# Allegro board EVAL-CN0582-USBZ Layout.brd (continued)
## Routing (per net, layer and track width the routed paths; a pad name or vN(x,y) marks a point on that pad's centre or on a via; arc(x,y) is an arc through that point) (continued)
SPI_MISO_FLASH: length 7.5
  TOP w0.203: R202.2 59.69,39.93 59.69,36.32 60.2,35.81 U2.2 62.87,35.81 R197.2
SPI_MOSI: length 176.8
  TOP w0.152: U18.18 41.12,51.64 41.28,51.79 41.28,52.83 40.64,53.47 v1(39.12,53.47)
  TOP w0.203: U12.8 41.15,64.52 v1(41.02,64.39) ; R201.1 v1(56.13,41.79) ; U20.2 77.48,94.04 76.33,92.89 76.33,92.74 76.07,92.49 76.07,86.89 76.45,86.51 76.45,83.66 77.17,82.95 v1(77.72,82.95) U19.6
  L3_SIG w0.152: v1(77.72,82.95) 77.71,82.93 76.7,82.93 76.29,83.34 74.66,83.34 72.78,81.46 69.31,81.46 59.05,71.2 59.05,55.88 56.64,53.47 v1(56.64,49.4) 56.64,45.13 57.53,44.24 57.53,41.71 57.24,41.43 56.49,41.43 v1(56.13,41.79) 55.88,41.53 55.88,41.2 57.91,39.17 57.91,32.14 59.77,30.29 59.77,25.09 60.93,23.93 60.93,18.2 60.2,17.46 60.2,13.72 56.16,9.68 43.44,9.68 42.81,9.05 42.81,6.87 42.8,6.86
  BOTTOM w0.152: v1(41.02,64.39) 40.72,64.08 40.72,55.07 v1(39.12,53.47) 39.12,52.96 40.23,51.84 47.76,51.84 48.77,50.83 55.47,50.83 56.64,49.66 v1(56.64,49.4) 56.64,48.84 57.76,47.73 U16.12 ; R177.2 TP28.1 37.85,6.22 38.61,5.46 41.4,5.46 42.8,6.86
SPI_MOSI_FLASH: length 5.2
  TOP w0.203: R201.2 56.13,38.61 55.88,38.35 U2.5 R210.2
SPI_RESET_FLASH: length 1.8
  TOP w0.203: U2.7 52.57,35.81 R209.2
SPI_SSN: length 60.3
  TOP w0.152: R175.2 40.13,12.28 40.13,11.43 41.32,10.24 v1(41.32,8.85)
  TOP w0.203: v1(55.09,42.27) 55.22,42.39 55.34,42.39 55.52,42.57 58.22,42.57 58.42,42.37 R204.1
  L3_SIG w0.152: v1(41.32,8.85) 41.57,8.85 43.14,10.41 55.84,10.41 59.49,14.06 59.49,17.68 60.27,18.47 60.27,23.65 59.11,24.82 59.11,30.01 57.23,31.89 57.23,38.82 54.86,41.18 54.86,42.04 v1(55.09,42.27)
SPI_SSN_FLASH: length 9.8
  TOP w0.203: R193.1 63,34.54 U2.1 59.18,34.54 58.42,35.31 R204.2
SPI_WP_FLASH: length 3
  TOP w0.203: U2.3 62.75,37.08 R194.1 R198.2
SS_DM: length 32.9
  TOP w0.152: FL1.C2 13.47,33.18 14.14,32.51 26.74,32.51 31.9,27.34 34.31,27.34 36.36,25.3 38.71,25.3 40.23,23.77 41.17,23.77 41.38,23.99 U1.A10
SS_DP: length 32.9
  TOP w0.152: FL1.C1 12.6,32.78 13.3,32.78 13.97,32.11 26.57,32.11 31.74,26.94 34.15,26.94 36.19,24.89 38.54,24.89 39.95,23.49 39.95,23.48 39.95,23.47 39.96,23.47 40.07,23.37 41.12,23.37 41.3,23.19 U1.A9
SS_RX_M: length 2.5
  BOTTOM w0.152: U35.14 20.01,27.06 20.4,27.06 20.55,26.91 20.55,26.4 21.05,25.91 21.22,25.91 C272.1
SS_RX_P: length 2.4
  BOTTOM w0.152: C271.1 21.48,26.42 21.11,26.42 20.95,26.57 20.95,27.08 20.56,27.47 U35.13
SS_TX_M: length 24.5
  TOP w0.152: v1(21.83,29.41) 22,29.24 24.71,29.24 arc(25.15,29.15) 25.52,28.9 25.56,28.86 arc(25.84,28.45) 25.93,27.96 25.93,23.26 arc(25.99,22.98) 26.14,22.75 27.94,20.96 arc(28.36,20.67) 28.86,20.57 36.68,20.57 arc(37.18,20.67) C141.2
  BOTTOM w0.152: U35.9 20.15,29.07 20.49,29.41 v1(21.83,29.41)
SS_TX_P: length 24.6
  TOP w0.152: v1(21.83,28.69) 21.96,28.83 24.71,28.83 arc(25,28.77) 25.24,28.61 25.27,28.58 arc(25.46,28.29) 25.53,27.96 25.53,23.24 arc(25.61,22.83) 25.84,22.48 27.65,20.67 arc(28.21,20.3) 28.86,20.17 37.05,20.17 arc(37.35,20.11) C142.2
  BOTTOM w0.152: v1(21.83,28.69) 21.52,29 20.66,29 20.32,28.66 20.01,28.66 U35.10
SYNC_IN: length 2.3
  TOP w0.203: R151.1 43.6,40.58 U18.36
SYS_HWRST: length 48.1
  TOP w0.203: v1(30.07,17.65) 29.82,17.4 20.07,17.4 19.29,16.62 19.29,12.56 16.13,9.4 12.32,9.4 11.18,10.53 C206.1 R208.2 9.12,10.38 D17.2 3.07,10.38 S2.2 ; U1.C5 v2(42.68,19.57)
  BOTTOM w0.127: v2(42.68,19.57) 42.44,19.57 42.05,19.18 41.99,19.18 41.98,19.18 41.32,19.18 41.25,19.1
  BOTTOM w0.152: 41.25,19.1 40.53,18.38 38.26,18.38
  BOTTOM w0.203: v1(30.07,17.65) 30.1,17.65 30.83,18.38 38.26,18.38
SYS_POWER: length 19.8
  TOP w0.305: C97.1 18.41,79.03 U13.6 ; v1(17.78,15.16) 17.88,15.27 18.57,15.27 18.67,15.37 18.67,12.89 18.49,12.71 R102.1 ; v1(14.48,72.9) 13.64,72.9 12.83,73.71 12.83,76.33 14.12,77.62 14.12,78.09 14.31,78.28 16.27,78.28 16.89,77.66 U13.8
  TOP w0.457: 30.86,88.52 30.85,88.53 U15.19
  TOP w0.508: v1(23.38,16.5) R274.2 v1(22.61,15.75)
  vias: v1(14.47,73.66) v1(14.48,72.01) v1(18.29,80.39) v1(18.54,15.19) v1(19.05,80.39) v1(23.37,41.91) v1(23.37,41.02) v1(24.26,41.02) v1(24.69,40.43) v1(25.53,64.26) v1(25.53,63.5) v1(29.59,84.84) v1(30.35,86.11) v1(30.35,85.47) v1(30.35,84.84)
TCK: length 65.6
  TOP w0.203: P7.4 23.11,5.59 v1(23.11,3.43) R207.1 ; U1.F6 v2(45.91,21.2)
  L3_SIG w0.127: 45.47,22.73 45.5,22.7 45.5,21.59 45.9,21.2 v2(45.91,21.2)
  L3_SIG w0.203: v1(23.11,3.43) 22.74,3.43 20.93,5.24 20.93,12.17 21.69,12.93 21.69,14.33 22,14.63 22,25.94 24.49,28.43 24.49,29.44 29.46,34.42 37.49,34.42 41.02,30.88 41.02,30.03 42.39,28.66 42.62,28.66 44.2,27.08 44.2,25.84 45.47,24.57 45.47,22.73
TDI: length 53
  TOP w0.203: P7.8 22.48,8.51 22.48,10.28 22.22,10.53 v1(22.22,10.92) R200.1 ; U1.E7 v2(44.28,22)
  L3_SIG w0.127: v2(44.28,22) 43.89,22.39 43.89,25.07 43.56,25.4
  L3_SIG w0.203: 43.56,25.4 42.29,26.67 42.29,27.68 40.26,29.71 40.26,30.57 37.17,33.66 29.78,33.66 25.68,29.55 25.68,15.74 22.22,12.29 v1(22.22,10.92)
TDO: length 52.8
  TOP w0.203: R206.1 v1(30.1,9.01) 29.33,9.01 27.85,7.53 26,7.53 P7.6 ; U1.C10 v2(42.68,24.4)
  L3_SIG w0.127: v2(42.68,24.4) 42.29,24.79 41.25,24.79 41.15,24.89
  L3_SIG w0.203: v1(30.1,9.01) 30.09,9.02 30.01,9.02 26.44,12.58 26.44,29.24 30.1,32.89 36.85,32.89 38.6,31.14 38.6,27.24 39.1,26.75 39.1,25.53 39.65,24.97 41.07,24.97 41.15,24.89
TMS: length 60.6
  TOP w0.203: U1.E8 v2(45.11,21.97) ; P7.2 21.72,5.21 v1(21.97,4.95) R229.1
  L3_SIG w0.203: v1(21.97,4.95) 21.31,5.61 21.31,11.91 25.3,15.9 25.3,29.71 29.62,34.04 37.33,34.04 40.64,30.72 40.64,29.87 42.67,27.84 42.67,26.83 44.72,24.78 44.72,22.37 v2(45.11,21.97)
TRIGGER: length 31.9
  TOP w0.203: P14.1 5.97,79.38 6.98,80.39 8.35,80.39 D13.2 9.68,80.42 9.91,80.64 11.18,80.64 R315.1 11.31,79.64 R333.2 R314.2 12.33,78.18 D8.A
  BOTTOM w0.203: P14.1 4.7,81.53 4.7,93.98 P5.1
TRST_N: length 50.5
  TOP w0.203: v2(41.83,25.2) 41.89,25.15 41.94,25.15 U1.B11 ; R199.1 21.08,11.3 21.84,10.54 v1(21.84,9.91) 21.72,9.78 P7.9
  L3_SIG w0.127: 40.52,25.37 41.17,25.37 41.34,25.2 v2(41.83,25.2)
  L3_SIG w0.203: v1(21.84,9.91) 22.35,9.91 22.76,10.31 22.76,11.2 26.06,14.5 26.06,29.4 29.94,33.27 37.01,33.27 38.98,31.3 38.98,27.4 39.48,26.91 39.48,25.69 39.79,25.37 40.52,25.37
TX1_N: length 2.1
  BOTTOM w0.152: U35.6 18.43,29.07 17.73,29.77 17.21,29.77 C253.2
TX1_P: length 2.1
  BOTTOM w0.152: U35.5 18.59,28.66 18.26,28.66 17.56,29.36 17.21,29.36 17.21,29.36 17.16,29.36 C251.2
TX2_N: length 5.2
  TOP w0.152: v1(18.94,29.85) 19.05,29.73 19.05,29.24 18.9,29.08 18.43,29.08 17.72,29.79 16.62,29.79 16.31,30.1 C254.2
  BOTTOM w0.152: U35.7 19.1,29.68 v1(18.94,29.85)
TX2_P: length 5.9
  TOP w0.152: v1(19.67,29.85) 19.46,29.63 19.46,29.07 19.07,28.68 18.27,28.68 18.24,28.7 18.24,28.7 17.55,29.39 16.62,29.39 16.31,29.08 C252.2
  BOTTOM w0.152: U35.8 19.51,29.18 19.51,29.69 v1(19.67,29.85)
TXVDDQ: length 6.4
  TOP w0.203: U1.B5 v2(41.88,19.57)
  BOTTOM w0.356: 40.9,19.93 41.15,19.68 41.77,19.68 v2(41.88,19.57)
  BOTTOM w0.508: E6.1 37.34,20.74 C149.2 39.32,20.74 C156.1 40.9,19.93
UNNAMED_22_ADP5071V2_I1_COMP1: length 5.3
  TOP w0.203: C109.1 R92.1 24.76,98.19 25.04,97.92 26.16,97.92 26.95,97.13 U15.8
UNNAMED_22_ADP5071V2_I1_COMP2: length 5.5
  TOP w0.203: U15.12 26.3,89.27 25.93,88.9 24.2,88.9 23.74,88.44 R94.1 23.62,87.64 C110.1
UNNAMED_22_ADP5071V2_I1_FB1: length 4.1
  TOP w0.203: R96.2 R97.1 27.05,97.64 27.6,97.09 U15.7
UNNAMED_22_ADP5071V2_I1_FB2: length 5
  TOP w0.203: R95.1 24.76,87.62 R93.2 24.9,88.27 25.15,88.52 26.09,88.52 26.29,88.52 26.95,89.18 U15.13
UNNAMED_22_ADP5071V2_I1_INBK: length 2.2
  TOP w0.406: U15.3 30.2,97.18 29.46,97.92
UNNAMED_22_ADP5071V2_I1_SEQ: length 10.4
  TOP w0.203: U15.5 28.9,97.21 28.45,97.66 v1(28.32,97.66)
  BOTTOM w0.203: R82.1 R83.2 22.48,97.79 23.11,97.16 27.81,97.16 v1(28.32,97.66)
UNNAMED_22_ADP5071V2_I1_SLEW: length 6.9
  TOP w0.203: U15.6 28.25,96.98 27.69,97.54 v1(27.69,98.04)
  BOTTOM w0.203: R85.2 R84.1 24.76,98.25 24.97,98.04 v1(27.69,98.04)
UNNAMED_22_ADP5071V2_I1_SS: length 6.4
  TOP w0.203: U15.10 22.43,96.06 21.34,97.16 R276.2
UNNAMED_22_ADP5071V2_I1_SW1: length 3.4
  TOP w0.508: U15.2 30.85,98.53 31.5,99.18
UNNAMED_22_ADP5071V2_I1_SYNC: length 5.5
  TOP w0.203: v1(28.07,98.81) 28.07,98.69 28.98,97.77 28.98,97.72 29.55,97.15 U15.4
  BOTTOM w0.203: v1(28.07,98.81) R87.2 R86.1
UNNAMED_22_ADP5071V2_I1_VREF: length 4.2
  TOP w0.203: U15.14 27.45,89.97 27.45,89.04 26.42,88.01 26.15,88.01 R93.1
  TOP w0.305: R93.1 25.91,87.75 C113.2
UNNAMED_22_ADP7118V2_I56_EN: length 6.2
  TOP w0.305: v1(42.55,98.3) R103.1
  TOP w0.508: U23.3 v1(45.78,98.11)
  BOTTOM w0.508: v1(45.78,98.11) 44.83,97.16 43.18,97.16 42.55,97.79 v1(42.55,98.3)
UNNAMED_22_ADP7118V2_I56_SENSE: length 2.7
  TOP w0.305: U23.4 49.3,97.26 49.28,97.24 R109.1 R110.1
UNNAMED_22_ADP7118V2_I56_VIN: length 1.6
  TOP w0.508: R103.2 43.52,99.94 C123.1
UNNAMED_22_ADP7118V2_I56_VOUT: length 5.3
  TOP w0.305: R109.2 v1(51.18,96.52)
  BOTTOM w0.305: v1(51.18,96.52) 51.82,96.52 52.32,97.03 v1(52.32,100.08)
UNNAMED_22_ADP7182V5_I66_ADJ: length 2.7
  TOP w0.305: R106.1 R105.1 51.05,91.19 U24.2
UNNAMED_22_ADP7182V5_I66_EN: length 1.5
  TOP w0.305: U24.3 50.03,92.02 R104.1
UNNAMED_22_ADP7182V5_I66_VOUT: length 4.4
  TOP w0.203: 52.71,89.92 53.47,89.92 53.62,90.07 53.62,92.3 53.47,92.45 R106.2
UNNAMED_22_CAP_I38_N1: length 1.5
  TOP w0.203: C112.1 22.35,87.37 R94.2
UNNAMED_22_CAP_I280_N1: length 1
  TOP w0.508: C111.1 24.76,100.83 R92.2
UNNAMED_22_CAP_I337_N1: length 21.4
  TOP w0.508: 7.49,27.05 7.5,27.06 M1.SH2 6.32,28.16 5.71,27.56 ; 2.6,27.8 M1.SH4 1.55,27.04 ; 1.55,37.54 M1.SH3 3.99,36.78 4.35,36.42 M1.SH1
  BOTTOM w0.508: 6.45,36.42 M1.SH1 7.5,37.18 ; 1.55,27.04 M1.SH4 ; M1.SH4 2.6,27.8 ; M1.SH4 1.55,28.56 ; M1.SH3 2.6,36.78 ; M1.SH3 1.55,37.54 ; M1.SH3 1.55,36.02 ; 6.45,28.16 M1.SH2 ; M1.SH2 7.5,28.92 ; M1.SH2 7.5,27.4
UNNAMED_22_CAP_I400_N1: length 8.2
  TOP w0.152: FL1.C3 13.71,33.58 v1(13.75,33.62)
  BOTTOM w0.152: C253.1 15.61,29.79 14.57,29.79 14,30.37 14,32 12.8,33.2 12.8,33.63 12.93,33.76 13.61,33.76 v1(13.75,33.62)
UNNAMED_22_CAP_I401_N1: length 9.7
  TOP w0.152: v1(13.71,34.33) 13.67,34.29 13.21,34.29 12.9,33.98 FL1.C4
  BOTTOM w0.152: v1(13.71,34.33) 13.54,34.16 12.76,34.16 12.4,33.8 12.4,33.03 13.59,31.83 13.59,30.2 14.4,29.39 15.58,29.39 C251.1
UNNAMED_22_CAP_I402_N1: length 2.4
  TOP w0.152: C252.1 14.17,29.08 13.86,29.39 13.39,29.39 13.17,29.17 12.6,29.17 FL2.C5
UNNAMED_22_CAP_I403_N1: length 2.4
  TOP w0.152: C254.1 13.96,30.1 13.65,29.79 13.22,29.79 13,29.57 FL2.C6
UNNAMED_22_ICCBTU02043_I388_XSD: length 4
  TOP w0.508: v1(16.76,28.3) 16.53,28.3 16.04,27.81 R296.2
  BOTTOM w0.203: U35.3 17.19,27.87 v1(16.76,28.3)
UNNAMED_22_ICPTN5150A_I359_ADR: length 1.6
  BOTTOM w0.203: R316.2 8.94,23.19 U36.5
UNNAMED_22_ICPTN5150A_I359_INTB: length 2
  BOTTOM w0.203: R317.1 9.68,23.59 U36.6
UNNAMED_22_ICPTN5150A_I359_PORT: length 2.9
  BOTTOM w0.203: R100.1 R292.2 9.42,22.39 U36.3
UNNAMED_22_ICPTN5150A_I359_VBUSDET: length 1.6
  BOTTOM w0.203: R101.1 8.73,22.79 U36.4
UNNAMED_23_74125V5_I307_A: length 1.6
  TOP w0.305: R349.1 32.26,32 U42.2
UNNAMED_23_ADLT8330_I322_FBX: length 4
  TOP w0.305: U13.1 16.48,75.76 16.16,75.44 R91.2 R90.1 C311.2
UNNAMED_23_ADLTC3112_I90_IOUT: length 1.9
  TOP w0.203: v1(24.66,65.4) 24.6,65.34 U30.8
  BOTTOM w0.203: v1(24.66,65.4) 24.64,65.38 R295.1
UNNAMED_23_ADLTC3112_I90_PWM: length 2.1
  TOP w0.152: U30.19 17.34,61.44 16.35,60.45 R294.1
UNNAMED_23_ADP1708_I291_ADJ: length 2.8
  TOP w0.203: R107.1 R108.2 13.62,12.08 U14.8
UNNAMED_23_ADP1708_I291_EN: length 1.6
  TOP w0.203: U14.1 16.36,13.72 16.48,13.72 16.48,13.69 17.91,13.69 R102.2
UNNAMED_23_ADP1708_I291_OUT: length 4.8
  TOP w0.203: R107.2 11.42,11.06 11.28,11.2 11.28,14.71 11.3,14.73
UNNAMED_23_ADP1708_I291_SENSE: length 1.8
  TOP w0.203: U14.7 13.16,14.23 12.27,13.34 R113.2
UNNAMED_23_ADP7118V2_I83_EN: length 4
  TOP w0.305: U31.3 33.25,56.24 33.47,56.45 33.47,57.91 33.24,58.14 U31.1
UNNAMED_23_ADP7118V2_I83_SENSE: length 3.2
  TOP w0.305: R158.2 R278.1 35.58,56.24 U31.4
UNNAMED_23_ADP7118V2_I83_VOUT: length 9.6
  TOP w0.305: R158.1 37.73,54.36 38.21,54.85 38.21,55.82 37.98,56.05 R293.2 ; U31.5 34.65,60.05 TP55.1
  TOP w0.508: R293.2 37.81,58.21 C227.1 34.72,58.21 U31.5
UNNAMED_23_ADP7142_I123_EN: length 9.2
  TOP w0.203: 28.96,80.07 28.96,81.28 29.08,81.41 32.77,81.41 33.16,81.01 U11.4
UNNAMED_23_ADP7142_I123_SS: length 1.3
  TOP w0.203: U11.5 C92.2
UNNAMED_23_CAP_I58_N2: length 1.9
  TOP w0.305: U30.18 17.28,62.09 16.79,61.59 C218.2
UNNAMED_23_CAP_I63_N2: length 7.5
  TOP w0.203: 30.35,65.53 30.35,63.37 31.37,62.36 31.37,60.41 31.17,60.21 C223.2 30.47,60.07 R289.2
UNNAMED_23_CAP_I65_N1: length 3
  TOP w0.203: C221.1 25.41,61.09 C222.2 25.05,61.44 U30.2
UNNAMED_23_CAP_I65_N2: length 1.1
  TOP w0.203: C221.2 R288.2
UNNAMED_23_CAP_I72_N1: length 1
  TOP w0.203: C223.1 30.6,61.21 R291.1
UNNAMED_23_CAP_I109_N1: length 1.1
  TOP w0.203: C95.1 33.74,71.73 R277.2
UNNAMED_23_CAP_I117_N2: length 1.6
  TOP w0.305: C100.2 17.91,78.49 U13.7
UNNAMED_23_CAP_I249_N2: length 3.1
  TOP w0.203: v1(19.68,44.32) v1(20.45,44.32) ; v1(19.81,48.13) v1(20.57,48.13)
  TOP w0.508: Q7.3 v1(19.68,44.32) ; Q8.3 v1(19.81,48.13)
  vias: v1(19.68,39.75) v1(20.32,39.75) v1(21.07,39.74)
UNNAMED_23_CAP_I257_N1: length 6.2
  TOP w0.508: Q7.2 17.97,45.26 C261.1 R328.1 16.07,45.26 Q5.2
UNNAMED_23_CAP_I257_N2: length 7.6
  TOP w0.508: Q5.1 16.07,43.38 R328.2 C261.2 17.97,43.38 Q7.1 22.29,43.38 22.35,43.44
UNNAMED_23_CAP_I260_N1: length 6.2
  TOP w0.508: Q6.2 16.07,49.07 C262.1 R329.1 17.97,49.07 Q8.2
UNNAMED_23_CAP_I260_N2: length 9.5
  TOP w0.203: 22.1,49.16 R327.1
  TOP w0.508: 22.1,49.16 22.1,47.55 21.74,47.19 Q8.1 17.97,47.19 R329.2 C262.2 16.07,47.19 Q6.1
UNNAMED_23_CAP_I272_N2: length 4.8
  TOP w0.508: R325.2 16.17,54.1 C260.2 16.94,53.33 R348.2 19.24,53.33 Q4.G
UNNAMED_23_CAP_I299_N1: length 0.9
  TOP w0.508: C287.1 R336.1
UNNAMED_23_CN2P_I240_N1: length 3.7
  TOP w0.508: 2.82,53.72 P12.1 ; P12.1 4.06,54.97 ; P12.1 5.31,53.72
UNNAMED_23_DIOLED_I278_P: length 1.5
  TOP w0.305: DS1.A R111.1
UNNAMED_23_RES_I270_N2: length 5.6
  TOP w0.508: R297.2 20.71,58.23 20.7,58.22 20.7,57.78 20.39,57.47 Q3.G 18.21,56.52 Q1.D
UNNAMED_23_RES_I295_N2: length 2.6
  TOP w0.508: Q4.D 22.35,51.93 R327.2
UNNAMED_23_RES_I296_N2: length 13.4
  TOP w0.508: Q3.D 22.99,56.52 23.49,56.01 23.49,46.74 22.35,45.59 R326.2
UNNAMED_24_ADA49451_I49_: length 3.6
  TOP w0.203: U9.4 75.96,73.82 77.08,74.94 C76.2 77.75,74.96 R70.2
UNNAMED_24_ADA49451_I49__1: length 3.4
  TOP w0.203: U9.3 76.42,73.32 77.04,73.94 C76.1 78.63,73.94 R66.2
UNNAMED_24_ADA49451_I49__2: length 3.4
  TOP w0.203: R65.2 78.67,72.14 C75.1 77.09,72.14 76.41,72.82 U9.2
UNNAMED_24_ADA49451_I49__3: length 3.6
  TOP w0.203: R69.2 78.63,71.14 C75.2 77.14,71.14 75.96,72.32 U9.1
UNNAMED_24_ADA49451_I49__4: length 1.8
  TOP w0.203: U9.10 71.58,73.32 R74.1
UNNAMED_24_ADA49451_I49__5: length 1.8
  TOP w0.203: R73.1 71.61,72.82 U9.11
UNNAMED_24_ADA49451_I63_: length 3.4
  TOP w0.203: R67.2 78.55,51.19 C77.1 76.96,51.19 76.29,51.86 U10.2
UNNAMED_24_ADA49451_I63__1: length 3.4
  TOP w0.203: R68.2 78.5,52.98 C78.1 76.91,52.98 76.29,52.36 U10.3
UNNAMED_24_ADA49451_I63__2: length 3.6
  TOP w0.203: R71.2 78.5,50.19 C77.2 77.01,50.19 75.83,51.36 U10.1
UNNAMED_24_ADA49451_I63__3: length 3.6
  TOP w0.203: U10.4 75.83,52.86 76.95,53.98 C78.2 77.62,54.01 R72.2
UNNAMED_24_ADA49451_I63__4: length 1.8
  TOP w0.203: R76.1 71.45,52.36 U10.10
UNNAMED_24_ADA49451_I63__5: length 1.8
  TOP w0.203: R75.1 71.48,51.86 U10.11
UNNAMED_24_ADLTC6910X_I158_AGND: length 5.4
  TOP w0.203: A10.2 v1(84.76,76.68)
  BOTTOM w0.203: R304.1 R298.1 R302.2 84.71,76.63 v1(84.76,76.68) 84.83,76.62 C226.1
UNNAMED_24_ADLTC6910X_I158_IN: length 8.7
  TOP w0.203: A10.3 85.78,77.31 A3.1 88.86,77.31 89.12,77.05 89.12,74.81 88.9,74.6 88.27,74.6 87.89,74.22 R55.2 C65.2
UNNAMED_24_ADLTC6910X_I158_OUT: length 3.6
  TOP w0.203: R57.1 86.86,74.35 v1(86.49,74.72) 85.75,75.46 A10.1
  BOTTOM w0.305: TP11.1 v1(86.49,74.72)
UNNAMED_24_ADLTC6910X_I163_AGND: length 5.4
  TOP w0.203: A11.2 v1(84.64,55.73)
  BOTTOM w0.203: C228.1 84.7,55.67 v1(84.64,55.73) 84.58,55.67 R303.2 R299.1 R305.1
UNNAMED_24_ADLTC6910X_I163_IN: length 8.8
  TOP w0.203: A11.3 85.65,56.35 A4.1 88.73,56.35 88.99,56.09 88.99,53.86 88.77,53.64 87.97,53.64 87.76,53.44 R56.2 C66.2
UNNAMED_24_ADLTC6910X_I163_OUT: length 3.6
  TOP w0.203: R58.1 86.73,53.4 v1(86.37,53.76) 85.63,54.5 A11.1
  BOTTOM w0.203: TP12.1 86.49,53.64 v1(86.37,53.76)
UNNAMED_24_CAP_I13_N2: length 2.9
  TOP w0.203: R43.2 C59.2 98.77,67.21 97.97,68.01 U7.5
UNNAMED_24_CAP_I35_N1: length 4
  TOP w0.203: C65.1 R55.1 R53.2 89.92,74.3 90.46,74.84 A3.4
UNNAMED_24_CAP_I37_N1: length 2.6
  TOP w0.203: R57.2 C71.1 R62.1
UNNAMED_24_CAP_I37_N2: length 2.5
  TOP w0.203: R59.2 C71.2 R61.1
UNNAMED_24_CAP_I42_N1: length 3.7
  TOP w0.203: R62.2 C73.1 R66.1 R70.1
UNNAMED_24_CAP_I42_N2: length 3.8
  TOP w0.203: R61.2 C73.2 R65.1 R69.1
UNNAMED_24_CAP_I67_N1: length 3.7
  TOP w0.203: R72.1 R68.1 C74.1 R64.2
UNNAMED_24_CAP_I67_N2: length 3.8
  TOP w0.203: R71.1 R67.1 C74.2 R63.2
UNNAMED_24_CAP_I71_N1: length 2.6
  TOP w0.203: R64.1 C72.1 R58.2
UNNAMED_24_CAP_I71_N2: length 2.5
  TOP w0.203: R60.2 C72.2 R63.1
UNNAMED_24_CAP_I83_N2: length 2.9
  TOP w0.203: R44.2 C60.2 98.64,58.95 97.84,59.75 U8.5
UNNAMED_24_CAP_I86_N1: length 4
  TOP w0.203: C66.1 R56.1 R54.2 89.8,53.35 90.34,53.89 A4.4
UNNAMED_24_RES_I182_N2: length 3.7
  TOP w0.508: A17.3 C307.1 87.69,65.46 R78.2 R7.2
UNNAMED_24_RES_I184_N2: length 3.7
  TOP w0.508: R264.2 R265.2 87.69,44.89 C308.1 A16.3
UNNAMED_25_ADA49451_I78_: length 3.6
  TOP w0.203: R35.2 78.63,32.63 C43.2 77.14,32.63 75.96,33.81 U21.1
UNNAMED_25_ADA49451_I78__1: length 3.6
  TOP w0.203: U21.4 75.96,35.31 77.08,36.43 C44.2 77.75,36.45 R36.2
UNNAMED_25_ADA49451_I78__2: length 3.4
  TOP w0.203: R31.2 78.67,33.63 C43.1 77.09,33.63 76.41,34.31 U21.2
UNNAMED_25_ADA49451_I78__3: length 3.4
  TOP w0.203: U21.3 76.42,34.81 77.04,35.43 C44.1 78.63,35.43 R32.2
UNNAMED_25_ADA49451_I78__4: length 1.8
  TOP w0.203: R40.1 71.58,34.81 U21.10
UNNAMED_25_ADA49451_I78__5: length 1.8
  TOP w0.203: U21.11 71.61,34.31 R39.1
UNNAMED_25_ADA49451_I92_: length 3.4
  TOP w0.203: R33.2 78.55,12.68 C45.1 76.96,12.68 76.29,13.35 U6.2
UNNAMED_25_ADA49451_I92__1: length 3.4
  TOP w0.203: R34.2 78.5,14.47 C46.1 76.91,14.47 76.29,13.85 U6.3
UNNAMED_25_ADA49451_I92__2: length 3.6
  TOP w0.203: U6.1 75.83,12.85 77.01,11.68 C45.2 78.5,11.68 R37.2
UNNAMED_25_ADA49451_I92__3: length 3.6
  TOP w0.203: R38.2 77.62,15.49 C46.2 76.95,15.47 75.83,14.35 U6.4
UNNAMED_25_ADA49451_I92__4: length 1.8
  TOP w0.203: R42.1 71.45,13.85 U6.10
UNNAMED_25_ADA49451_I92__5: length 1.8
  TOP w0.203: U6.11 71.48,13.35 R41.1
UNNAMED_25_ADLTC6910X_I163_AGND: length 5.4
  TOP w0.203: A12.2 v1(84.76,38.17)
  BOTTOM w0.203: R309.1 R300.1 R307.2 84.71,38.12 v1(84.76,38.17) 84.83,38.11 C231.1
UNNAMED_25_ADLTC6910X_I163_IN: length 8.7
  TOP w0.203: A12.3 85.78,38.8 A1.1 88.86,38.8 89.12,38.54 89.12,36.3 88.9,36.08 88.27,36.08 87.89,35.71 R21.2 C33.2
UNNAMED_25_ADLTC6910X_I163_OUT: length 3.6
  TOP w0.203: A12.1 85.75,36.94 v1(86.49,36.21) 86.86,35.84 R23.1
  BOTTOM w0.305: TP5.1 v1(86.49,36.21)
UNNAMED_25_ADLTC6910X_I168_AGND: length 5.4
  TOP w0.203: A13.2 v1(84.64,17.22)
  BOTTOM w0.203: C232.1 84.7,17.15 v1(84.64,17.22) 84.58,17.16 R306.2 R301.1 R308.1
UNNAMED_25_ADLTC6910X_I168_IN: length 8.7
  TOP w0.203: A13.3 85.65,17.84 A2.1 88.73,17.84 88.99,17.58 88.99,15.35 88.77,15.13 88.14,15.13 87.76,14.76 R22.2 C34.2
UNNAMED_25_ADLTC6910X_I168_OUT: length 3.6
  TOP w0.203: R24.1 86.73,14.88 v1(86.37,15.25) 85.63,15.99 A13.1
  BOTTOM w0.203: v1(86.37,15.25) 86.49,15.13 TP4.1
UNNAMED_25_CAP_I38_N1: length 4
  TOP w0.203: C33.1 R21.1 R19.2 89.92,35.82 90.46,36.36 A1.4
UNNAMED_25_CAP_I41_N2: length 2.9
  TOP w0.203: U4.5 97.97,29.49 98.77,28.69 C27.2 R9.2
UNNAMED_25_CAP_I53_N1: length 2.6
  TOP w0.203: R24.2 C40.1 R30.1
UNNAMED_25_CAP_I53_N2: length 2.5
  TOP w0.203: R26.2 C40.2 R29.1
UNNAMED_25_CAP_I56_N1: length 3.7
  TOP w0.203: R30.2 C42.1 R34.1 R38.1
UNNAMED_25_CAP_I56_N2: length 3.8
  TOP w0.203: R29.2 C42.2 R33.1 R37.1
UNNAMED_25_CAP_I70_N1: length 2.6
  TOP w0.203: R23.2 C39.1 R28.1
UNNAMED_25_CAP_I70_N2: length 2.5
  TOP w0.203: R27.1 C39.2 R25.2
UNNAMED_25_CAP_I74_N1: length 3.7
  TOP w0.203: R36.1 R32.1 C41.1 R28.2
UNNAMED_25_CAP_I74_N2: length 3.8
  TOP w0.203: R27.2 C41.2 R31.1 R35.1
UNNAMED_25_CAP_I94_N2: length 2.9
  TOP w0.203: R10.2 C28.2 98.64,20.44 97.84,21.24 U5.5
UNNAMED_25_RES_I15_N2: length 4
  TOP w0.203: C34.1 R22.1 R20.2 89.8,14.99 90.34,15.53 A2.4
UNNAMED_25_RES_I181_N1: length 2.3
  TOP w0.305: Q9.D 102.85,7.49 R341.1
UNNAMED_25_RES_I185_N2: length 3.7
  TOP w0.508: R358.2 R359.2 87.82,27.33 C310.1 A18.3
UNNAMED_25_RES_I187_N2: length 3.7
  TOP w0.508: R266.2 R267.2 87.69,5.87 C309.1 A19.3
UNNAMED_26_ADG5436_I1_EN: length 2.3
  TOP w0.305: U22.12 93.09,69.58 R279.2
UNNAMED_26_ADG5436_I1_S1B: length 2.4
  TOP w0.203: C119.2 98.49,72.52 U22.2
UNNAMED_26_ADG5436_I1_S2B: length 2.3
  TOP w0.305: U22.10 93.07,73.15 91.82,73.15 91.39,72.72 R281.2
UNNAMED_26_ADG5436_I1_VSS: length 3.7
  TOP w0.203: U22.3 97.78,73.17 99.05,74.45 R360.2 R362.1
UNNAMED_26_ADG5436_I17_EN: length 2.3
  TOP w0.305: R280.2 92.96,48.62 U27.12
UNNAMED_26_ADG5436_I17_S1B: length 2.5
  TOP w0.203: U27.2 98.43,51.56 C120.2
UNNAMED_26_ADG5436_I17_S2B: length 2.3
  TOP w0.203: U27.10 92.94,52.2 91.69,52.2 91.26,51.76 R282.2
UNNAMED_26_ADG5436_I17_VSS: length 3.7
  TOP w0.203: U27.3 97.61,52.21 R361.2 R363.1
UNNAMED_26_ADG5436_I20_EN: length 2.3
  TOP w0.305: R283.2 93.09,31.07 U28.12
UNNAMED_26_ADG5436_I20_S1B: length 2.5
  TOP w0.203: C131.2 98.59,34.01 U28.2
UNNAMED_26_ADG5436_I20_S2B: length 2.3
  TOP w0.203: U28.10 93.07,34.64 91.82,34.64 91.39,34.21 R285.2
UNNAMED_26_ADG5436_I20_VSS: length 3.5
  TOP w0.203: U28.3 97.48,34.66 R364.2 R366.1
UNNAMED_26_ADG5436_I29_EN: length 2.3
  TOP w0.305: U29.12 92.96,10.11 R284.2
UNNAMED_26_ADG5436_I29_S1B: length 2.4
  TOP w0.203: C153.2 98.4,13.05 U29.2
UNNAMED_26_ADG5436_I29_S2B: length 2.3
  TOP w0.203: U29.10 92.94,13.69 91.69,13.69 91.26,13.25 R286.2
UNNAMED_26_ADG5436_I29_VSS: length 3.5
  TOP w0.203: R367.1 R365.2 97.58,13.7 U29.3
UNNAMED_27_AD55X3_I1_IOUT: length 18.9
  TOP w0.203: U20.5 73.61,95.34 73.44,95.5 73.4,95.5 73.34,95.56 71.06,95.56 70.36,96.27 70.36,98.55 70.61,98.81 C193.2 72.02,100.53 72.58,101.09 74.3,101.09 77.16,98.23 A8.2
UNNAMED_27_AD9833_I8_CAP: length 4.3
  TOP w0.305: CAP2.5.1 70.73,84.07 C181.2 C180.1 73.14,83.95 U19.3
UNNAMED_27_AD9833_I8_COMP: length 1.6
  TOP w0.203: C178.1 75.05,85.72 74.66,85.33 U19.1
UNNAMED_27_AD9833_I8_MCLK: length 2
  TOP w0.203: R153.1 73.76,82.04 U19.5
UNNAMED_27_AD9833_I8_VOUT: length 3.7
  TOP w0.305: R154.1 79.37,85.72 79.01,85.36 U19.10 79.99,84.95 v1(80.14,85.09)
  BOTTOM w0.305: R343.1 79.78,85.45 v1(80.14,85.09)
UNNAMED_27_ADA45221_I217_: length 6.9
  TOP w0.305: v1(80.01,88.65) R155.2 R156.1 80.47,89.97 A7.2
  BOTTOM w0.305: C291.1 79.83,86.49 80.14,86.79 80.14,88.52 v1(80.01,88.65) 80.02,88.65 C292.1
UNNAMED_27_ADA45221_I217__1: length 8.4
  TOP w0.305: A7.3 77.92,90.62 77.22,89.92 v1(77.22,88.52) TP29.1 77.47,87.88 R157.2 R154.2
  BOTTOM w0.305: R344.2 76.57,87.88 v1(77.22,88.52)
UNNAMED_27_ADA45221_I223_: length 6
  TOP w0.305: R312.1 97.29,96.39 96.96,96.72 A14.2 94.04,96.72 R318.2
UNNAMED_27_ADA45221_I223_OUT: length 9.4
  TOP w0.203: R351.2 103.29,94.37 103.05,94.61 TP59.1
  TOP w0.305: R312.2 98.29,95.75 98.61,96.07 A14.6 100.22,96.07 D4.3 TP59.1
UNNAMED_27_ADA45221_I227_: length 5.7
  TOP w0.203: C185.2 92.34,90.85 94.46,90.85 94.47,90.86 A5.3
  TOP w0.305: R160.2 91.64,90.26 C185.2
UNNAMED_27_ADG1219_I151_D: length 5.2
  TOP w0.203: U32.6 92.32,96.07 TP57.1 92.57,96.07 A14.3
UNNAMED_27_ADG1219_I151_EN: length 2.9
  TOP w0.305: R310.2 87.89,98.8 88.06,98.63 U32.1
UNNAMED_27_ADG1219_I151_SB: length 20
  TOP w0.305: v1(103.21,90.84) C216.1 102.09,90.86 A5.6 ; U32.5 90.5,93.8 TP32.1 90.42,92.96 90.94,92.45 v1(92.01,92.45) R112.1
  BOTTOM w0.305: v1(92.01,92.45) 93.62,90.84 v1(103.21,90.84)
UNNAMED_27_CAP_I189_N2: length 7.9
  TOP w0.305: v1(79.25,88.65) 79.37,88.53 R157.1 80.26,87.88 R148.2 C244.1 82.55,87.62 83.11,87.06 C243.2 R311.1
  BOTTOM w0.305: v1(79.25,88.65) 79.37,88.53 R345.1
UNNAMED_27_CAP_I238_N2: length 1
  BOTTOM w0.305: R343.2 C291.2
UNNAMED_27_CAP_I250_N2: length 16.7
  TOP w0.305: v1(90.17,87.76) R160.1 R159.2 ; C216.2 v1(103.04,89.24)
  BOTTOM w0.305: v1(103.04,89.24) 91.66,89.24 v1(90.17,87.76)
UNNAMED_27_CNBNC2P_I81_CNTR: length 5.6
  TOP w0.203: R351.1 D5.2 D4.4
  TOP w0.305: D5.2 J6.1
UNNAMED_27_DIO4PV11_I83_A1: length 1.5
  TOP w0.203: v1(102.74,97.63) D4.1
  BOTTOM w0.305: R121.2 102.74,97.63 v1(102.74,97.63)
UNNAMED_27_DIO4PV11_I83_K2: length 1.1
  TOP w0.203: R228.2 101.99,97.92 D4.2
UNNAMED_27_RES_I13_N2: length 3.4
  TOP w0.203: R153.2 70.46,82.04 70.33,82.17 Y4.3
UNNAMED_27_RES_I119_N2: length 2.8
  TOP w0.203: A5.2 94.04,91.51 R99.2 R112.2
UNNAMED_28_AD568XRV5_I11_VREF: length 4
  BOTTOM w0.305: U16.15 59.95,50.44 C146.2 60.04,52.01 R128.1
UNNAMED_28_AD77684_I28_AVDD1A: length 16.2
  TOP w0.203: U18.4 v1(48.1,55.34)
  TOP w0.254: U18.4 48.1,53.07 48.16,53.01 48.16,52.47 48.1,52.41 U18.45
  BOTTOM w0.305: v1(48.1,55.34) 47.49,55.95 C163.1 C164.1 47.41,57.36 E2.2
UNNAMED_28_AD77684_I28_AVDD2A: length 10.4
  TOP w0.203: U18.60 50.26,50.14 v1(50.04,49.91) ; U18.53 v1(50.24,46.64)
  BOTTOM w0.508: E3.2 47.04,49.78 C166.1 C165.1 49.9,49.78 v1(50.04,49.91) 50.67,49.91 51.05,49.53 51.05,47.45 v1(50.24,46.64)
UNNAMED_28_AD77684_I28_DIN: length 2.2
  TOP w0.203: U18.21 38.45,50.14 R150.2
UNNAMED_28_AD77684_I28_DNC: length 2.2
  TOP w0.203: U18.20 38.38,50.64 R258.1
UNNAMED_28_AD77684_I28_DREGCAP: length 3.2
  TOP w0.203: C171.1 C169.1 42.66,41.62 42.6,41.68 U18.34
UNNAMED_28_AD77684_I28_IOVDD: length 4.7
  TOP w0.203: U18.35 v1(43.1,43.99)
  BOTTOM w0.508: v1(43.1,43.99) 43.19,43.9 C168.2 C167.2 43.19,40.69 E4.1
UNNAMED_28_AD77684_I28_PINN: length 7.1
  TOP w0.203: R149.2 53.6,49.2 53.93,49.53 55,49.53 ; U18.57 52.83,48.64
  TOP w0.305: 55,49.53 55.63,49.53 56.9,50.8 TP7.1
  TOP w0.508: 52.83,48.64 52.83,48.64 R149.2
UNNAMED_28_AD77684_I28_REG1CAPA: length 3.2
  TOP w0.254: C175.1 C174.1 53.3,50.64 U18.61
UNNAMED_28_AD77684_I28_REG2CAPB: length 3.3
  TOP w0.254: 53.21,46.14 U18.52
  TOP w0.508: 53.21,46.14 53.59,45.76 C172.1 C173.1
UNNAMED_28_AD77684_I28_SYNCOUTN: length 2.3
  TOP w0.203: U18.38 44.6,41.58 44.69,41.49 R151.2
UNNAMED_28_ADA48071_I285_: length 10.7
  TOP w0.508: A6.4 v1(53.61,56.71) ; R139.1 49.24,59.26 C152.1 v1(49.24,61.35)
  L3_SIG w0.508: v1(49.24,61.35) 49.24,60.24 52.77,56.71 v1(53.61,56.71)
UNNAMED_28_ADA48071_I285__1: length 1.4
  TOP w0.508: R132.2 50.98,56.71 A6.3
UNNAMED_28_ADA48071_I292_: length 2.7
  TOP w0.635: R143.2 R142.1 50.73,66.23 A9.4
UNNAMED_28_ADA48071_I307_: length 2.6
  TOP w0.508: R195.2 C101.1 57.58,60.18 A15.4
UNNAMED_28_ADA48071_I307_DISABLEN: length 1.6
  TOP w0.508: R319.1 57.41,59.11 58.49,59.11 A15.5
UNNAMED_28_ADA48071_I307_VOUT: length 12.7
  TOP w0.508: C101.2 R195.1 v1(56.27,61.91) ; v1(62.49,57.37) R253.1 62.43,58.28 A15.1
  BOTTOM w0.508: v1(56.27,61.91) 58.39,61.91 62.49,57.81 v1(62.49,57.37)
UNNAMED_28_CAP_I178_N1: length 6.4
  TOP w0.508: 29.34,46.86 C12.1 30.49,46.31 E16.2 ; 29.34,46.86 R6.1 ; 29.34,46.86 29.29,46.82 Y3.4
UNNAMED_28_CAP_I209_N1: length 5
  TOP w0.508: E17.2 34.41,51.4 C13.1 R77.1 34.41,46.99 Y5.4
UNNAMED_28_CAP_I254_N2: length 3
  TOP w0.508: C152.2 50.84,58.88 R138.1 51.04,58.61 A6.1
UNNAMED_28_CAP_I282_N2: length 3
  TOP w0.635: C154.2 58.84,66.2 R131.2 R135.1
UNNAMED_28_NCTESTPAD_I237_N1: length 5.3
  TOP w0.203: R256.1 55.51,47.51 57.41,49.41 TP18.1
  TOP w0.508: R257.1 R256.1 55.51,46.23 R255.2
UNNAMED_28_RES_I152_N2: length 2.5
  TOP w0.635: R135.2 56.9,66.3 R254.1 55.81,66.23 A9.3
UNNAMED_28_RES_I334_N1: length 1.8
  TOP w0.203: R373.1 Y3.3
UNNAMED_28_RES_I335_N2: length 3
  TOP w0.203: Q10.G 29.41,48.45 29.84,48.01 R374.1 R372.2
UNNAMED_28_RES_I336_N2: length 3.7
  TOP w0.203: Y5.1 33.41,46.73 R77.2 32.64,48.26 32.38,48.01 R374.2
UNNAMED_28_RES_I338_N2: length 4.8
  TOP w0.203: Y3.1 27.09,46.83 R6.2 26.81,47.11 Q10.D
UNNAMED_28_RES_I341_N1: length 1.7
  TOP w0.203: Y5.3 34.67,44.71 R375.1
UNNAMED_29_ADP1708_I198_ADJ: length 2.8
  TOP w0.203: U26.8 30.48,15.86 R227.1 30.95,16.34 R226.1
UNNAMED_29_ADP1708_I198_EN: length 1.4
  TOP w0.203: R224.1 25.65,15.86 U26.1
UNNAMED_29_ADP1708_I198_IN: length 2.2
  TOP w0.203: R274.1 R275.1 25.39,14.6 R224.2
UNNAMED_29_ADP1708_I198_SENSE: length 1.5
  TOP w0.203: U26.7 30.56,15.36 R225.2
UNNAMED_29_CAP_I53_N1: length 3
  TOP w0.152: U1.A5 41.16,19.99 40.96,20.18 39.19,20.18 arc(38.87,20.12) C142.1
UNNAMED_29_CAP_I54_N1: length 3.1
  TOP w0.152: U1.A6 41.16,20.79 40.96,20.59 39.48,20.59 arc(39.01,20.68) C141.1
UNNAMED_29_CAP_I143_N1: length 11.9
  TOP w0.152: U1.E10 44.28,24.4 44.28,24.96 43.25,25.98
  TOP w0.203: D6.C 39.24,30.93 C90.1 R231.2 40.27,28.19 42.29,26.16 42.82,26.16 43,25.98 43.25,25.98
UNNAMED_29_CAP_I208_N2: length 24.9
  TOP w0.152: v1(24.26,24.38) 24.09,24.21 arc(24.04,24.15) 24.03,24.08 24.03,21.84 arc(24.22,20.88) 24.76,20.07 arc(25.81,19.37) 27.03,19.13 ; 27.03,19.13 27.03,19.13 ; 27.03,19.13 arc(27.03,19.13) 27.03,19.13 ; 27.03,19.13 34.54,19.13 arc(34.78,19.1) 35.02,19.02 arc(35.07,19) 35.14,18.99 40.96,18.99 41.16,19.19 U1.A4
  BOTTOM w0.152: C271.2 22.95,26.19 23.56,26.19 24.02,25.73 24.02,25.1 24.26,24.86 v1(24.26,24.38)
UNNAMED_29_CAP_I209_N2: length 24.8
  TOP w0.152: v1(23.37,24.38) 23.62,24.13 23.62,24.13 arc(23.62,24.1) 23.62,24.08 23.62,21.84 arc(23.84,20.73) 24.48,19.78 arc(25.65,19) 27.03,18.72 34.54,18.72 arc(34.69,18.7) 34.84,18.65 arc(34.98,18.6) 35.14,18.58 40.96,18.58 41.16,18.39 U1.A3
  BOTTOM w0.152: C272.2 22.85,25.78 23.39,25.78 23.61,25.56 23.61,25.1 23.37,24.86 v1(23.37,24.38)
UNNAMED_29_DIOSCHOTTKY_I142_P: length 33.8
  TOP w0.508: P8.2 58.8,24.77 59.44,24.13 61.59,24.13 62.1,24.64 62.1,31.24 61.09,32.26 52.45,32.26 51.64,33.07 42.21,33.07 41.27,32.12 R231.1
UNNAMED_29_ICCYUSB301X_I1_CLKIN: length 6.2
  TOP w0.203: U1.D7 v2(43.48,22)
  BOTTOM w0.127: 41.22,24.36 41.4,24.18 41.54,24.18 41.72,23.99 42.05,23.99 42.28,23.76 42.28,23.39 42.47,23.21 42.94,23.21 43.08,23.07 43.08,22.41 v2(43.48,22)
  BOTTOM w0.203: 41.22,24.36 40.56,25.02 TP1.1
UNNAMED_29_ICCYUSB301X_I1_GPIO: length 7.5
  TOP w0.203: U1.J6 v2(48.31,21.2)
  BOTTOM w0.152: v2(48.31,21.2) 48.86,20.65 51.01,20.65 52.92,22.56 R140.2
UNNAMED_29_ICCYUSB301X_I1_GPIO_1: length 7.3
  TOP w0.152: R133.2 53.68,27.01 53.21,26.54 52.2,26.54 50.03,24.38 49.09,24.38 U1.K10
UNNAMED_29_ICCYUSB301X_I1_GPIO_2: length 7.4
  TOP w0.203: U1.F7 v2(45.91,22)
  BOTTOM w0.152: v2(45.91,22) 45.1,22.81 45.1,24.91 45.09,24.92 45.09,25.08 44.55,25.61 44.55,26.61 44.28,26.89 44.28,27.86 44.08,28.05 R120.2
UNNAMED_29_ICCYUSB301X_I1_GPIO_3: length 4.4
  TOP w0.152: R268.2 46.48,25.79 46.74,25.54 46.74,24.42 U1.G10
UNNAMED_29_ICCYUSB301X_I1_GPIO_4: length 5.3
  TOP w0.203: U1.G9 v2(46.71,23.6)
  BOTTOM w0.152: v2(46.71,23.6) 46.71,26.59 47.23,27.12 R122.2
UNNAMED_29_ICCYUSB301X_I1_GPIO_5: length 5.5
  TOP w0.152: U1.H10 47.51,24.4 47.51,25.54 47.93,25.96 47.93,25.97 48.25,26.29 48.9,26.29 49.53,26.93 R124.2
UNNAMED_29_ICCYUSB301X_I1_GPIO_6: length 5.4
  TOP w0.203: U1.F9 v2(45.91,23.6)
  BOTTOM w0.152: R119.2 45.13,27.47 45.34,27.26 45.34,27.25 45.47,27.12 45.47,25.08 45.48,25.07 45.48,24.37 45.91,23.94 v2(45.91,23.6)
UNNAMED_29_ICCYUSB301X_I1_GPIO_7: length 8.2
  TOP w0.203: U1.J8 v2(48.31,22.8)
  BOTTOM w0.152: R136.2 53.38,26.97 49.22,22.8 v2(48.31,22.8)
UNNAMED_29_ICCYUSB301X_I1_GPIO_8: length 5.3
  TOP w0.152: R134.2 51.69,24.77 50.49,23.57 49.08,23.57 U1.K9
UNNAMED_29_ICCYUSB301X_I1_GPIO_9: length 6.5
  TOP w0.203: U1.G8 v2(46.71,22.8)
  BOTTOM w0.127: 47.12,24.66 47.12,23.21 v2(46.71,22.8)
  BOTTOM w0.203: 47.12,24.66 47.9,25.45 47.9,26.57 48.28,26.95 R137.2
UNNAMED_29_ICCYUSB301X_I1_GPIO_10: length 9.1
  TOP w0.203: U1.G6 v2(46.71,21.2)
  BOTTOM w0.127: 49.92,22.1 49.58,21.76 49.57,21.76 49.41,21.59 47.1,21.59 v2(46.71,21.2)
  BOTTOM w0.152: R152.2 53.78,23.21 52.8,23.21 51.69,22.1 49.92,22.1
UNNAMED_29_ICCYUSB301X_I1_GPIO_11: length 5.5
  TOP w0.152: R144.2 52.3,20.62 51.08,21.84 50.51,21.84 50.25,22.1 49.87,22.1 49.78,22 49.12,22 U1.K7
UNNAMED_29_ICCYUSB301X_I1_GPIO_12: length 7.2
  TOP w0.203: U1.D4 v2(43.48,18.77)
  BOTTOM w0.127: v2(43.48,18.77) 43.48,18.53 43.88,18.14 43.88,17.81 43.23,17.16 43.23,17.14
  BOTTOM w0.152: R174.1 41.22,13.5 43.18,15.46 43.18,17.09 43.23,17.14
UNNAMED_29_ICCYUSB301X_I1_GPIO_13: length 6
  TOP w0.152: U1.C2 42.72,17.2 42.72,16.6 42.05,15.94 41.5,15.94 39.5,13.94 39.5,13.7 R176.1
UNNAMED_29_ICCYUSB301X_I1_GPIO_14: length 4.7
  TOP w0.152: R175.1 40.3,14.01 41.79,15.5 42.08,15.5 43.1,16.52 U1.C1
UNNAMED_29_ICCYUSB301X_I1_GPIO_15: length 7.1
  TOP w0.203: U1.D3 v2(43.48,17.97)
  BOTTOM w0.152: v2(43.48,17.97) 42.8,17.29 42.8,15.54 41.73,14.48 40.64,14.48 40.17,14.01 R273.1
UNNAMED_29_ICCYUSB301X_I1_GPIO_16: length 5.2
  TOP w0.152: R173.1 41.35,14.31 43.52,16.47 43.52,17.2 U1.D2
UNNAMED_29_ICCYUSB301X_I1_GPIO_17: length 10.3
  TOP w0.203: U1.D5 v2(43.48,19.57)
  BOTTOM w0.127: 40.16,17.5 40.38,17.72 40.96,17.72 41.61,18.37 42.04,18.37 42.28,18.61 42.28,18.98 42.47,19.17 43.08,19.17 v2(43.48,19.57)
  BOTTOM w0.152: R177.1 38.74,14.35 39.33,14.35 39.88,14.9 39.88,17.21 40.16,17.5
UNNAMED_29_ICCYUSB301X_I1_GPIO_18: length 4
  TOP w0.152: U1.D1 43.9,16.38 42.42,14.9 42.42,13.47 R172.1
UNNAMED_29_ICCYUSB301X_I1_GPIO_19: length 8.2
  TOP w0.203: U1.C4 v2(42.68,18.77)
  BOTTOM w0.127: v2(42.68,18.77) 42.68,18.53 42.29,18.14 42.29,17.45 42.42,17.32
  BOTTOM w0.152: R270.1 39.03,13.5 40.39,14.86 41.54,14.86 42.42,15.74 42.42,17.32
UNNAMED_29_ICCYUSB301X_I1_GPIO_20: length 7.8
  TOP w0.203: U1.E5 v2(44.28,19.57)
  BOTTOM w0.127: 43.88,18.59 43.88,19.17 v2(44.28,19.57)
  BOTTOM w0.152: R219.1 42.27,14.08 43.56,15.37 43.56,17.02 44.19,17.66 44.19,18.27 43.88,18.59
UNNAMED_29_ICCYUSB301X_I1_GPIO_21: length 6.8
  TOP w0.203: U1.E4 v2(44.28,18.77)
  BOTTOM w0.127: 44.83,18.23 v2(44.28,18.77)
  BOTTOM w0.152: 44.83,18.23 44.83,17.02 44.12,16.31 44.12,14.25 R171.1
UNNAMED_29_ICCYUSB301X_I1_GPIO_22: length 8.8
  TOP w0.203: U1.H4 v2(47.51,18.77)
  BOTTOM w0.127: v2(47.51,18.77) 47.9,18.38 47.9,17.81 48.17,17.54
  BOTTOM w0.152: R169.1 49.76,15.96 48.17,17.54
UNNAMED_29_ICCYUSB301X_I1_GPIO_23: length 7.9
  TOP w0.203: U1.H5 v2(47.51,19.57)
  BOTTOM w0.127: v2(47.51,19.57) 47.9,19.18 49.4,19.18 49.86,18.72
  BOTTOM w0.152: R271.1 52.03,19.26 51.49,18.72 49.86,18.72
UNNAMED_29_ICCYUSB301X_I1_GPIO_24: length 5.9
  TOP w0.152: U1.L4 50.8,17.88 50.8,17.02 52.31,15.5 R170.1
UNNAMED_29_ICCYUSB301X_I1_GPIO_25: length 6.5
  TOP w0.203: U1.F4 v2(45.91,18.77)
  BOTTOM w0.152: R215.1 45.42,14.01 44.96,14.48 44.96,16.12 45.5,16.67 45.5,18.14 45.85,18.49 45.85,18.72 v2(45.91,18.77)
UNNAMED_29_ICCYUSB301X_I1_GPIO_26: length 7.3
  TOP w0.203: U1.F5 v2(45.91,19.57)
  BOTTOM w0.127: v2(45.91,19.57) 45.91,19.35 45.5,18.94 45.5,18.62
  BOTTOM w0.152: R232.1 44.48,13.56 44.48,16.11 45.17,16.8 45.17,18.28 45.47,18.57 45.47,18.58 45.5,18.62
UNNAMED_29_ICCYUSB301X_I1_GPIO_27: length 6.6
  TOP w0.152: U1.F2 45.08,17.17 45.08,16.64 43.75,15.3 43.75,13.52 43.84,13.43 44.61,13.43 44.96,13.08 R272.1
UNNAMED_29_ICCYUSB301X_I1_GPIO_28: length 4.7
  TOP w0.152: 47.75,15.88 47.75,16.18 47.52,16.41 47.52,17.16 U1.H2
  TOP w0.203: R213.1 48.51,13.46 48.51,14.48 47.75,15.24 47.75,15.88
UNNAMED_29_ICCYUSB301X_I1_GPIO_29: length 4
  TOP w0.152: R212.1 49.53,13.48 49.53,14.6 48.08,16.05 48.08,16.33 47.9,16.52 U1.J1
UNNAMED_29_ICCYUSB301X_I1_GPIO_30: length 5.4
  TOP w0.203: U1.F3 v2(45.91,17.97)
  BOTTOM w0.152: R218.1 45.85,14.08 45.85,17.91 v2(45.91,17.97)
UNNAMED_29_ICCYUSB301X_I1_GPIO_31: length 8.7
  TOP w0.203: U1.H3 v2(47.51,17.97)
  BOTTOM w0.152: v2(47.51,17.97) 47.51,17.74 50.21,15.04 54.06,15.04 R214.1
UNNAMED_29_ICCYUSB301X_I1_GPIO_32: length 4.9
  TOP w0.152: 46.36,15.49 45.92,15.93 45.92,17.22 46.29,17.59 U1.G2
  TOP w0.203: 46.36,15.49 46.74,15.11 46.74,15.03 46.94,14.82 46.94,13.96 R216.1
UNNAMED_29_ICCYUSB301X_I1_GPIO_33: length 5.9
  TOP w0.203: U1.G3 v2(46.71,17.97)
  BOTTOM w0.152: v2(46.71,17.97) 46.71,17.6 48.57,15.74 R217.1
UNNAMED_29_ICCYUSB301X_I1_GPIO_34: length 4.8
  TOP w0.152: U1.E1 44.52,16.61 44.52,16.54 43.33,15.35 43.33,13.15 R233.1
UNNAMED_29_ICCYUSB301X_I1_GPIO_35: length 7.2
  TOP w0.203: U1.J3 v2(48.31,17.97)
  BOTTOM w0.152: R161.1 53.51,17.06 53.09,16.64 49.65,16.64 v2(48.31,17.97)
UNNAMED_29_ICCYUSB301X_I1_GPIO_36: length 7
  TOP w0.203: U1.G4 v2(46.71,18.77)
  BOTTOM w0.127: v2(46.71,18.77) 46.32,18.38 46.32,17.53
  BOTTOM w0.152: R168.1 47.52,13.49 48.01,13.97 48.01,15.84 46.32,17.53
UNNAMED_29_ICCYUSB301X_I1_GPIO_37: length 6.7
  TOP w0.152: U1.K2 49.12,17.17 49.12,16.54 52.2,13.46 R220.1
UNNAMED_29_ICCYUSB301X_I1_GPIO_38: length 6.8
  TOP w0.203: U1.J4 v2(48.31,18.77)
  BOTTOM w0.127: v2(48.31,18.77) 48.7,18.38 50.3,18.38
  BOTTOM w0.152: R221.1 52.85,18.16 52.79,18.1 51.27,18.1 50.99,18.38 50.3,18.38
UNNAMED_29_ICCYUSB301X_I1_GPIO_39: length 6.7
  TOP w0.152: U1.K1 48.74,16.74 48.74,16.41 52.74,12.41 R222.1
UNNAMED_29_ICCYUSB301X_I1_GPIO_40: length 5.3
  TOP w0.152: R223.1 50.6,14.06 48.41,16.26 48.41,16.47 48.31,16.57 48.31,17.17 U1.J2
UNNAMED_29_ICCYUSB301X_I1_GPIO_41: length 4.5
  TOP w0.152: R118.2 45.72,27.69 45.72,25.16 45.87,25.02 45.87,24.35 U1.F10
UNNAMED_29_ICCYUSB301X_I1_GPIO_42: length 4.6
  TOP w0.152: U1.L10 50.27,23.99 52.11,25.82 R130.2
UNNAMED_29_ICCYUSB301X_I1_GPIO_43: length 5.6
  TOP w0.152: U1.K11 48.85,24.94 48.86,24.94 49.7,25.78 50.8,25.78 52.63,27.61 R129.2
UNNAMED_29_ICCYUSB301X_I1_GPIO_44: length 6.8
  TOP w0.203: U1.J9 v2(48.31,23.6)
  BOTTOM w0.203: R127.2 51.44,26.03 49,23.6 v2(48.31,23.6)
UNNAMED_29_ICCYUSB301X_I1_GPIO_45: length 6.1
  TOP w0.152: R126.2 51.58,27.33 50.55,26.29 49.67,26.29 48.29,24.91 48.29,24.38 U1.J10
UNNAMED_29_ICCYUSB301X_I1_GPIO_46: length 5.8
  TOP w0.203: U1.H9 v2(47.51,23.6)
  BOTTOM w0.203: v2(47.51,23.6) 47.51,24.14 49.28,25.91 49.28,28.02 R125.2
UNNAMED_29_ICCYUSB301X_I1_GPIO_47: length 6.3
  TOP w0.203: U1.F8 v2(45.91,22.8)
  BOTTOM w0.127: v2(45.91,22.8) 46.3,23.19 46.3,24.12
  BOTTOM w0.152: 46.3,24.12 45.86,24.56 45.86,26.55 46.18,26.88 R123.2
UNNAMED_29_ICCYUSB301X_I1_GPIO_48: length 6.6
  TOP w0.152: R165.2 52.03,16.55 51.31,17.27 51.31,18.22 49.96,19.57 49.12,19.57 U1.K5
UNNAMED_29_ICCYUSB301X_I1_GPIO_49: length 7.2
  TOP w0.203: U1.J5 v2(48.31,19.57)
  BOTTOM w0.152: v2(48.31,19.57) 49.46,19.57 49.92,19.11 51.26,19.11 52.51,20.36 R166.2
UNNAMED_29_ICCYUSB301X_I1_GPIO_50: length 8.8
  TOP w0.203: U1.H6 v2(47.51,21.2)
  BOTTOM w0.152: R164.2 52.96,21.46 51.03,19.53 49.96,19.53 49.48,20.02 48.69,20.02 v2(47.51,21.2)
UNNAMED_29_ICCYUSB301X_I1_GPIO_51: length 11.4
  TOP w0.203: U1.G5 v2(46.71,19.57)
  BOTTOM w0.127: 47.44,17.34 47.12,17.66 47.12,17.81 47.12,17.81 47.12,19.17 v2(46.71,19.57)
  BOTTOM w0.152: 51.02,13.76 47.44,17.34
  BOTTOM w0.203: R163.2 51.02,13.76
UNNAMED_29_ICCYUSB301X_I1_GPIO_52: length 7.1
  TOP w0.203: U1.H8 v2(47.51,22.8)
  BOTTOM w0.127: 48.01,24.1 47.92,24.01 47.92,23.41 47.51,23 v2(47.51,22.8)
  BOTTOM w0.203: 48.01,24.1 48.42,24.51 48.42,24.51 49.81,25.9 49.81,27.44 50.38,28.01 R162.2
UNNAMED_29_ICCYUSB301X_I1_GPIO_53: length 10.8
  TOP w0.203: U1.G7 v2(46.71,22)
  BOTTOM w0.127: v2(46.71,22) 47.12,22.41 47.67,22.41 47.92,22.65 47.92,22.96 48.15,23.19 48.48,23.19 48.5,23.22
  BOTTOM w0.152: R147.2 53.97,28.07 49.12,23.22 48.5,23.22
UNNAMED_29_ICCYUSB301X_I1_GPIO_54: length 8.9
  TOP w0.203: U1.H7 v2(47.51,22)
  BOTTOM w0.127: 50.55,23.65 49.3,22.39 48.15,22.39 48.13,22.38 48.08,22.38 47.7,22 v2(47.51,22)
  BOTTOM w0.152: 50.55,23.65 52.77,25.87 R146.2
UNNAMED_29_ICCYUSB301X_I1_GPIO_55: length 7.7
  TOP w0.203: U1.J7 v2(48.31,22)
  BOTTOM w0.152: R145.2 53.44,24.77 51.26,22.58 49.94,22.58 49.42,22.06 49.41,22.06 49.35,22 v2(48.31,22)
UNNAMED_29_ICCYUSB301X_I1_GPIO_56: length 5
  TOP w0.152: R141.2 53.23,22.61 50.71,22.61 50.51,22.8 49.12,22.8 U1.K8
UNNAMED_29_ICCYUSB301X_I1_GPIO_57: length 5.3
  TOP w0.152: R269.2 51.93,19.57 50.98,20.52 50.24,20.52 50.09,20.37 49.11,20.37 U1.K6
UNNAMED_29_ICCYUSB301X_I1_I2CGPIO: length 8.5
  TOP w0.203: U1.D10 v2(43.48,24.4)
  BOTTOM w0.127: v2(43.48,24.4) 43.24,24.4 42.85,24.79 42.52,24.79 42.26,25.05 42.26,25.49 42.13,25.63
  BOTTOM w0.152: R235.1 40.61,28.59 40.61,27.9 40.64,27.87 40.64,27.86 40.85,27.65 40.85,25.83 41.05,25.63 42.13,25.63
UNNAMED_29_ICCYUSB301X_I1_I2CGPIO_1: length 8.3
  TOP w0.203: U1.D9 v2(43.48,23.6)
  BOTTOM w0.127: 41.39,24.81 42.03,24.81 42.28,24.56 42.28,24.25 42.52,24 43.08,24 v2(43.48,23.6)
  BOTTOM w0.152: R234.1 40.17,28.58 40.28,28.46 40.28,27.76 40.31,27.74 40.31,27.72 40.52,27.51 40.52,25.68 41.39,24.81
UNNAMED_29_ICCYUSB301X_I1_O: length 6
  TOP w0.203: TP3.1 39.47,28.45 42.13,25.78 42.67,25.78 42.84,25.6 43.08,25.6 U1.D11
UNNAMED_29_ICCYUSB301X_I1_RUSB2: length 2.5
  TOP w0.203: U1.C8 v2(42.68,22.8)
  BOTTOM w0.127: v2(42.68,22.8) 42.44,22.8 42.05,23.19 41.57,23.19 R178.2
UNNAMED_29_ICCYUSB301X_I1_RUSB3: length 3.8
  TOP w0.152: 40.39,17.97 41.88,17.97
  TOP w0.203: R167.2 38.84,17.97 40.39,17.97 ; 41.88,17.97 U1.B3
UNNAMED_30_CN10P_I90_N1: length 4.4
  TOP w0.203: R230.1 20.83,3.56 21.08,3.81 21.08,6.1 P7.1
UNNAMED_30_DIOLED_I129_N: length 1.7
  TOP w0.305: R182.1 2.53,65.83 DS2.C
UNNAMED_30_RES_I2_N1: length 1.6
  TOP w0.203: Y2.3 32.05,25.24 R183.1
UNNAMED_30_RES_I10_N2: length 1.6
  TOP w0.305: Y2.1 29.97,24.01 R180.2
UNNAMED_30_RES_I76_N1: length 1.5
  TOP w0.152: R191.1 55.5,4.95 S1.1B
UNNAMED_30_RES_I130_N2: length 1.9
  TOP w0.305: R182.2 2.77,67.81 Q2.D
UNNAMED_30_RES_I131_N2: length 2.1
  TOP w0.203: Q2.G 5.9,66.85 5.7,66.65 R181.2
UNNAMED_31_74LVC1G04_I124_A: length 10.5
  TOP w0.203: U37.5 9.66,89.53 R334.1 5.96,88.38 3.43,85.85 3.43,84.66 3.23,84.45 U38.2
UNNAMED_31_74LVC1G04_I124_Y: length 20.9
  TOP w0.203: R340.2 17.91,85.98 17.65,85.72 16.33,85.72 16.13,85.52 16.13,84.68 U41.2 v1(16,83.19) ; v1(5.52,84.38) 5.84,84.38 5.89,84.33 6.09,84.33 R335.1 6.27,84.07 5.71,83.51 U38.4
  BOTTOM w0.203: v1(16,83.19) 14.81,84.38 v1(5.52,84.38)
UNNAMED_31_74LVC1G04_I136_Y: length 1.8
  TOP w0.203: R339.2 16.95,88.47 U41.4
UNNAMED_31_ADG839_I121_S1: length 11.3
  TOP w0.203: P5.2 9.89,92.61 R338.2 R337.1 9.91,90.24 U37.4 8.59,90.18 D19.2
UNNAMED_31_ADLTC4332_I1_LINKN: length 4.9
  TOP w0.203: U12.5 38.94,67.19 38.73,66.99 38.73,64.97 37.34,63.58 R249.2
UNNAMED_31_ADLTC4332_I1_REMOTE: length 4.8
  TOP w0.203: R239.1 R244.1 38.1,65.71 38.31,65.91 38.31,67.23 38.77,67.7 U12.4
UNNAMED_31_ADLTC4332_I1_SPEED1: length 3.4
  TOP w0.203: U12.14 45.22,68.19 R242.1 R243.2
UNNAMED_31_ADLTC4332_I1_SPEED2: length 4.5
  TOP w0.203: U12.15 44.06,68.7 44.32,68.96 44.32,69.59 R240.1 R241.2
UNNAMED_31_ADLTC4332_I1_SSCN: length 5.1
  TOP w0.203: R245.2 R352.2 38.44,63.84 39.51,64.91 U12.6
UNNAMED_31_ADLTC4332_I1_VCC: length 28.6
  TOP w0.305: U12.1 39.14,69.19 38.86,69.47 ; v1(41.4,63.13) R248.2
  TOP w0.508: R249.1 v1(35.54,63.58) ; v1(37.76,72.2) C17.1 37.72,71.21 R247.1 38.36,69.97 38.86,69.47
  BOTTOM w0.508: v1(41.4,63.13) 41.91,63.63 41.91,64.9 41.02,65.79 40.01,65.79 39.62,66.17 39.62,70.87 38.29,72.2 v1(37.76,72.2) 36.22,70.66 35.53,70.66 34.8,69.93 34.8,64.14 35.36,63.58 v1(35.54,63.58)
UNNAMED_31_CAP_I93_N2: length 8.9
  TOP w0.203: R333.1 10.29,78.75 10.04,78.49 D8.C 11.48,77.93 11.68,77.72 11.68,75.18 11.54,75.04 C240.2 10.47,74.89 U3.4
UNNAMED_31_ICMAX7312_I57_AD0: length 3.2
  TOP w0.152: R323.2 R324.1 v1(73.43,44.25)
  BOTTOM w0.203: U40.21 v1(73.43,44.25)
UNNAMED_31_ICMAX7312_I57_I: length 4.1
  BOTTOM w0.203: TP60.1 77.11,40.49 77.11,40.49 76.73,40.87 76.24,40.87 76.03,41.07 U40.17
UNNAMED_31_ICMAX7312_I57_I_1: length 6
  BOTTOM w0.203: TP61.1 76.96,39.12 76.96,40.1 76.65,40.41 76.05,40.41 75.38,41.08 U40.18
UNNAMED_31_ICMAX7312_I57_I_2: length 6
  BOTTOM w0.203: U40.20 74.08,41.74 74.17,41.66 74.17,41.65 74.19,41.62 74.19,39.34 75.31,38.23 TP65.1
UNNAMED_31_ICMAX7312_I57_I_3: length 3.7
  BOTTOM w0.203: U40.19 74.73,41.19 75.89,40.03 75.92,40.03 TP64.1
UNNAMED_31_ICMAX14595_I66_TSN: length 1.6
  TOP w0.305: U39.4 69.73,40.65 R320.1
UNNAMED_31_RES_I83_N1: length 9.4
  TOP w0.203: R314.1 13.33,79.68 13.97,80.32 13.97,84.45 12.83,85.6 11.53,85.6 11.3,85.83 U33.2
UNNAMED_31_RES_I116_N1: length 4.8
  TOP w0.508: Y6.1 16.44,98.65 16.72,98.93 R331.1 R332.2 18.03,99.06 R330.2
VOCM: length 110.4
  TOP w0.508: R358.1 v1(86.73,24.98) ; R264.1 v1(86.61,42.29) ; R7.1 86.62,63.38 v1(86.62,63.37) ; R266.1 v1(86.61,4.06)
  TOP w0.635: R142.2 v1(48.78,66.42) ; v1(86.62,63.37) 85.98,62.74 TP24.1 57.24,62.78 C154.1 56.99,64.14 C270.1 55.36,64.14 55.18,64.33 A9.1 v1(54.41,63.3)
  L3_SIG w0.508: v1(86.62,63.37) 86.23,63.37 85.73,62.86 85.73,55.01 84.71,53.99 84.71,47.67 86.63,45.75 86.63,42.31 v1(86.61,42.29) 86.61,39.89 87.76,38.73 87.76,35.76 85.38,33.39 85.38,26.89 86.73,25.54 v1(86.73,24.98) 86.49,24.74 86.49,19.18 87.32,18.34 87.32,14.55 86.61,13.83 v1(86.61,4.06)
  BOTTOM w0.635: v1(54.41,63.3) 51.29,66.42 v1(48.78,66.42)
VOCM_ADC: length 94
  TOP w0.508: TP25.1 64.66,58.12 C268.1 64.52,58.22 R253.2 ; R359.1 v1(87.88,24.98) ; R265.1 v1(87.76,42.29) ; R78.1 v1(87.76,63.37) ; R267.1 v1(87.76,4.06)
  TOP w0.635: v1(87.76,63.37) 87.76,62.2 85.98,60.43 72.49,60.43 70.18,58.12 TP25.1
  L3_SIG w0.508: v1(87.76,4.06) 87.76,4.54 88.32,5.09 88.32,13 88.9,13.59 88.9,21.59 88.18,22.31 88.18,24.69 v1(87.88,24.98) 87.88,28.12 87,29.01 87,33.4 88.9,35.31 88.9,41.78 88.39,42.29 v1(87.76,42.29) 87.76,49.83 88.32,50.39 88.32,55.45 87,56.77 87,62.48 87.76,63.25 v1(87.76,63.37)
VREF: length 72
  TOP w0.305: TP21.1 v1(62.81,70.48) ; TP21.1 61.98,67.69 60.58,66.29 R131.1 ; TP21.1 61.97,70.48 C269.1 C145.1 57.54,70.48 U17.6 ; v1(61.34,53.34) 55.88,53.34 53.47,55.75 50.86,55.75 50.54,56.07 50.46,56.07 49.92,56.62 R132.1 R88.1
  L3_SIG w0.305: v1(62.81,70.48) 67.18,66.12 67.18,59.18 v1(61.34,53.34)
  BOTTOM w0.305: R345.2 77.92,87.5 77.53,87.12 77.53,86.04 74.8,83.31 72.77,83.31 63.75,74.3 63.75,71.42 v1(62.81,70.48) ; R128.2 v1(61.34,53.34)
VREG: length 34.2
  TOP w0.305: U15.16 28.9,88.83 v1(28.96,88.77)
  BOTTOM w0.508: C98.2 v1(28.96,88.77) 28.96,88.47 28.45,87.96 22.4,87.96 19.94,90.42 19.94,99.31 20.45,99.81 R82.2 21.46,99.94 21.46,101.98 22.05,102.57 25.58,102.57 TP2.1 R86.2 R84.2
XTAL_IN: length 14.3
  TOP w0.152: Y1.1 35.04,28.81 C202.1 v1(36.19,28.95)
  TOP w0.203: U1.C6 v2(42.68,21.2)
  L3_SIG w0.127: v2(42.68,21.2) 42.29,21.59 42.04,21.59 42.03,21.59 41.72,21.59 41.72,21.59 41.66,21.59
  L3_SIG w0.203: v1(36.19,28.95) 36.45,28.69 36.45,27.75 37.95,26.25 37.95,24.53 40.89,21.59 41.66,21.59
XTAL_OUT: length 16.4
  TOP w0.152: Y1.3 32.62,30.16 33.25,29.53 34.73,29.53 C204.1 v1(36.19,29.98)
  TOP w0.203: U1.C7 v2(42.68,22)
  L3_SIG w0.127: v2(42.68,22) 42.29,22.39 41.66,22.39
  L3_SIG w0.203: v1(36.19,29.98) 36.83,29.34 36.83,27.91 38.33,26.41 38.33,24.69 40.67,22.35 41.62,22.35 41.66,22.39

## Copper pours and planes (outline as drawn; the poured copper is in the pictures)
5V_SUPPLY on TOP (solid shape): 91.95,59.07 91.95,56.28 91.82,56.15 89.66,56.15 89.53,56.28 89.53,59.2 91.82,59.2
5V_SUPPLY on TOP (solid shape): 91.95,20.56 91.95,17.76 91.82,17.64 89.66,17.64 89.53,17.76 89.53,20.69 91.82,20.69
5V_SUPPLY on TOP (solid shape): 92.08,80.03 92.08,77.23 91.95,77.1 89.79,77.1 89.66,77.23 89.66,80.15 91.95,80.15
5V_SUPPLY on TOP (solid shape): 92.08,41.51 92.08,38.72 91.95,38.59 89.79,38.59 89.66,38.72 89.66,41.64 91.95,41.64
5V_SUPPLY on TOP (solid shape): 74.55,56.66 74.55,54.86 74.44,54.71 74.41,54.52 74.43,54.38 74.5,54.25 74.51,54.23 74.51,54.13 74.5,54.11 74.45,54.01 74.44,53.91 74.44,53.32 74.44,53.23 73.28,53.23 73.03,53.48 73.03,56.78 73.15,56.91 74.3,56.91
5V_SUPPLY on TOP (solid shape): 74.55,18.15 74.55,16.34 74.44,16.19 74.41,16.01 74.43,15.87 74.5,15.74 74.51,15.72 74.51,15.61 74.5,15.6 74.45,15.5 74.44,15.39 74.44,14.81 74.44,14.72 73.28,14.72 73.03,14.97 73.03,18.27 73.15,18.4 74.3,18.4
5V_SUPPLY on TOP (solid shape): 74.68,77.61 74.68,75.81 74.57,75.66 74.53,75.48 74.56,75.33 74.63,75.2 74.64,75.19 74.64,75.08 74.63,75.07 74.58,74.97 74.56,74.86 74.56,74.28 74.56,74.18 73.41,74.18 73.15,74.44 73.15,77.74 73.28,77.87 74.42,77.87
5V_SUPPLY on TOP (solid shape): 74.68,39.1 74.68,37.3 74.57,37.15 74.53,36.97 74.56,36.82 74.63,36.69 74.64,36.68 74.64,36.57 74.63,36.56 74.58,36.46 74.56,36.35 74.56,35.76 74.56,35.67 73.41,35.67 73.15,35.93 73.15,39.23 73.28,39.35 74.42,39.35
5V_SUPPLY on TOP: 54.38,61.39 54.38,58.34 54.46,58.27 55.45,58.27 55.6,58.42 55.6,61.26 55.47,61.39
5V_SUPPLY on TOP: 38.61,57.02 38.61,59.44 39.24,60.07 44.45,60.07 44.58,59.94 44.58,58.93 40.01,58.93 39.62,58.55 39.62,57.02 39.5,56.9 38.73,56.9
5V_SUPPLY on TOP: 59.56,30.1 59.56,24.64 61.47,24.64 61.72,24.89 61.72,29.97 61.59,30.1
5V_SUPPLY on L4_SIG: 70.74,96.01 98.04,96.01 98.04,88.65 98.12,88.47 98.3,88.39 118.74,88.39 118.74,0.64 59.82,0.64 59.82,31.12 71.75,31.12 71.93,31.19 72.01,31.37 72.01,43.56 71.93,43.74 71.75,43.81 62.99,43.81 62.99,56.64 62.92,56.82 62.74,56.9 44.43,56.9 42.8,58.53 42.8,61.59 48.26,61.59 48.44,61.67 48.51,61.85 48.51,74.17 62.48,74.17 62.48,64.39 62.56,64.21 62.74,64.14 92.08,64.14 92.08,53.59 88.77,53.59 88.59,53.52 88.52,53.34 88.52,49.28 88.59,49.1 88.77,49.02 92.08,49.02 92.08,36.07 88.9,36.07 88.72,35.99 88.65,35.81 88.65,31.88 88.72,31.7 88.9,31.62 92.08,31.62 92.08,14.99 88.65,14.99 88.47,14.91 88.39,14.73 88.39,10.67 88.47,10.49 88.65,10.41 106.68,10.41 106.86,10.49 106.93,10.67 106.93,73.91 106.86,74.09 106.68,74.17 70.61,74.17 70.61,80.01 70.54,80.19 70.36,80.26 69.85,80.26 69.85,89.03 71.63,89.03 71.81,89.1 71.88,89.28 71.88,92.58 71.81,92.76 71.63,92.84 70.74,92.84
5V_USB on TOP: 7.24,37.72 7.37,37.59 13.08,37.59 13.46,37.97 13.46,44.7 13.34,44.83 7.11,44.83 7.11,43.05 7.24,42.93
